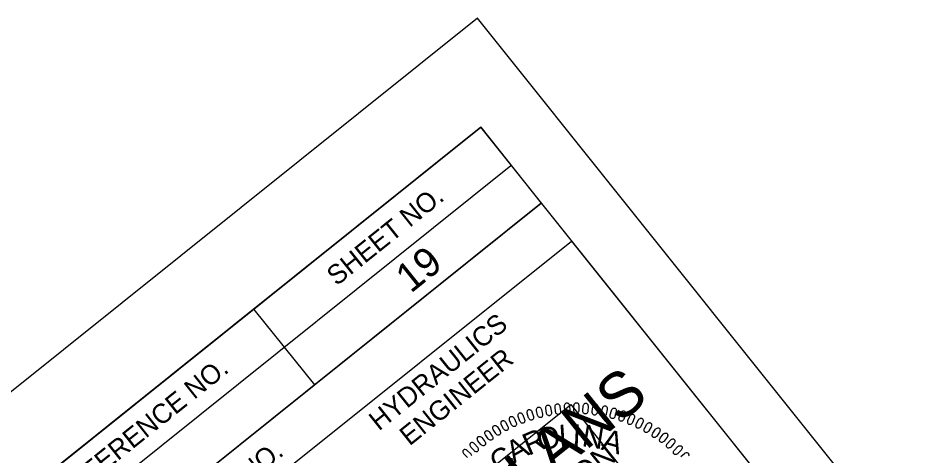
# Model space of a CAD drawing. Extents: x 472510 to 474509, y 505091 to 506998.
# Drawn here: x 473706 to 473939.9, y 506885.2 to 506998.1 of the extents above; entities that cross this region are included whole.
import ezdxf

# ---------------------------------------------------------------- set-up
doc = ezdxf.new("R2010")
doc.units = 0
for name, color, linetype in [('Sheet Data Field CELL', 7, 'Continuous'), ('Sheet PE Seal Cell', 7, 'Continuous'), ('Sheet Plan CELL', 7, 'Continuous'), ('Sheet Plot Border Outside CELL', 7, 'Continuous'), ('Sheet Sticker Incomplete CELL', 7, 'Continuous')]:
    doc.layers.add(name, color=color, linetype=linetype)

msp = doc.modelspace()

# ---------------------------------------------------------------- linework, layer by layer
at = {"layer": 'Sheet PE Seal Cell'}
for points in [[(473847.16, 506896.85), (473847.11, 506898.07), (473847.13, 506898.29), (473847.18, 506898.44), (473847.28, 506898.61), (473847.38, 506898.72), (473847.48, 506898.81), (473847.59, 506898.85), (473847.7, 506898.88), (473847.81, 506898.86), (473847.93, 506898.84), (473848.04, 506898.78), (473848.15, 506898.69), (473848.21, 506898.61), (473848.29, 506898.47), (473848.35, 506898.29), (473848.38, 506898.13), (473848.45, 506896.88), (473848.44, 506896.71), (473848.4, 506896.56), (473848.32, 506896.4), (473848.21, 506896.26), (473848.12, 506896.17), (473847.96, 506896.11), (473847.81, 506896.08), (473847.66, 506896.11), (473847.56, 506896.16), (473847.42, 506896.25), (473847.3, 506896.41), (473847.22, 506896.59), (473847.19, 506896.72)], [(473849.53, 506896.92), (473849.55, 506898.15), (473849.59, 506898.37), (473849.64, 506898.51), (473849.76, 506898.68), (473849.86, 506898.78), (473849.97, 506898.86), (473850.08, 506898.9), (473850.19, 506898.92), (473850.3, 506898.9), (473850.42, 506898.87), (473850.52, 506898.8), (473850.63, 506898.7), (473850.69, 506898.62), (473850.75, 506898.47), (473850.81, 506898.29), (473850.83, 506898.13), (473850.81, 506896.87), (473850.79, 506896.7), (473850.74, 506896.57), (473850.65, 506896.41), (473850.53, 506896.27), (473850.44, 506896.19), (473850.28, 506896.13), (473850.13, 506896.12), (473849.98, 506896.16), (473849.88, 506896.21), (473849.75, 506896.31), (473849.63, 506896.48), (473849.57, 506896.67), (473849.54, 506896.8)], [(473851.86, 506896.85), (473851.96, 506898.07), (473852.01, 506898.29), (473852.07, 506898.42), (473852.2, 506898.58), (473852.3, 506898.69), (473852.42, 506898.76), (473852.53, 506898.79), (473852.64, 506898.8), (473852.75, 506898.77), (473852.87, 506898.73), (473852.97, 506898.66), (473853.07, 506898.55), (473853.12, 506898.47), (473853.17, 506898.32), (473853.22, 506898.13), (473853.23, 506897.97), (473853.14, 506896.72), (473853.1, 506896.55), (473853.05, 506896.42), (473852.94, 506896.26), (473852.82, 506896.13), (473852.72, 506896.06), (473852.56, 506896.01), (473852.41, 506896.01), (473852.26, 506896.06), (473852.16, 506896.12), (473852.04, 506896.23), (473851.93, 506896.4), (473851.88, 506896.59), (473851.86, 506896.72)], [(473837.83, 506895.02), (473837.47, 506896.2), (473837.45, 506896.42), (473837.45, 506896.57), (473837.51, 506896.76), (473837.57, 506896.9), (473837.66, 506897), (473837.75, 506897.07), (473837.85, 506897.13), (473837.96, 506897.14), (473838.08, 506897.15), (473838.2, 506897.12), (473838.33, 506897.05), (473838.41, 506897), (473838.52, 506896.87), (473838.63, 506896.72), (473838.7, 506896.57), (473839.07, 506895.37), (473839.1, 506895.2), (473839.1, 506895.06), (473839.06, 506894.88), (473838.99, 506894.71), (473838.92, 506894.61), (473838.79, 506894.5), (473838.65, 506894.44), (473838.5, 506894.44), (473838.38, 506894.45), (473838.23, 506894.51), (473838.07, 506894.64), (473837.95, 506894.79), (473837.89, 506894.91)], [(473840.17, 506895.7), (473839.88, 506896.89), (473839.87, 506897.11), (473839.89, 506897.26), (473839.96, 506897.45), (473840.02, 506897.58), (473840.12, 506897.68), (473840.21, 506897.75), (473840.31, 506897.79), (473840.43, 506897.8), (473840.55, 506897.8), (473840.66, 506897.76), (473840.79, 506897.69), (473840.87, 506897.63), (473840.97, 506897.5), (473841.07, 506897.34), (473841.13, 506897.19), (473841.43, 506895.97), (473841.44, 506895.8), (473841.43, 506895.65), (473841.38, 506895.47), (473841.3, 506895.31), (473841.23, 506895.21), (473841.09, 506895.12), (473840.95, 506895.06), (473840.8, 506895.07), (473840.68, 506895.09), (473840.53, 506895.16), (473840.38, 506895.3), (473840.27, 506895.45), (473840.21, 506895.57)], [(473842.46, 506896.23), (473842.25, 506897.44), (473842.25, 506897.66), (473842.28, 506897.81), (473842.36, 506897.99), (473842.44, 506898.12), (473842.53, 506898.22), (473842.63, 506898.27), (473842.74, 506898.31), (473842.85, 506898.31), (473842.97, 506898.3), (473843.09, 506898.26), (473843.21, 506898.18), (473843.28, 506898.11), (473843.37, 506897.98), (473843.46, 506897.81), (473843.51, 506897.66), (473843.73, 506896.42), (473843.74, 506896.25), (473843.72, 506896.1), (473843.66, 506895.93), (473843.57, 506895.78), (473843.49, 506895.68), (473843.34, 506895.59), (473843.2, 506895.55), (473843.05, 506895.56), (473842.94, 506895.59), (473842.79, 506895.67), (473842.65, 506895.82), (473842.55, 506895.98), (473842.5, 506896.11)], [(473844.81, 506896.59), (473844.67, 506897.81), (473844.69, 506898.03), (473844.72, 506898.18), (473844.82, 506898.36), (473844.9, 506898.48), (473845, 506898.57), (473845.1, 506898.62), (473845.21, 506898.65), (473845.33, 506898.64), (473845.45, 506898.63), (473845.56, 506898.58), (473845.67, 506898.49), (473845.74, 506898.42), (473845.83, 506898.28), (473845.91, 506898.11), (473845.94, 506897.95), (473846.09, 506896.7), (473846.08, 506896.53), (473846.06, 506896.39), (473845.98, 506896.22), (473845.89, 506896.07), (473845.8, 506895.98), (473845.65, 506895.9), (473845.5, 506895.87), (473845.35, 506895.89), (473845.24, 506895.93), (473845.1, 506896.01), (473844.97, 506896.17), (473844.88, 506896.34), (473844.84, 506896.46)], [(473854.28, 506896.62), (473854.45, 506897.83), (473854.52, 506898.04), (473854.59, 506898.17), (473854.73, 506898.33), (473854.84, 506898.42), (473854.96, 506898.48), (473855.07, 506898.51), (473855.18, 506898.51), (473855.29, 506898.48), (473855.41, 506898.43), (473855.5, 506898.36), (473855.59, 506898.24), (473855.64, 506898.16), (473855.68, 506898), (473855.72, 506897.81), (473855.72, 506897.65), (473855.55, 506896.41), (473855.5, 506896.24), (473855.44, 506896.11), (473855.32, 506895.96), (473855.19, 506895.84), (473855.09, 506895.78), (473854.92, 506895.74), (473854.77, 506895.74), (473854.63, 506895.8), (473854.53, 506895.87), (473854.42, 506895.98), (473854.33, 506896.17), (473854.29, 506896.36), (473854.27, 506896.49)], [(473856.63, 506896.26), (473856.88, 506897.46), (473856.96, 506897.67), (473857.04, 506897.8), (473857.18, 506897.94), (473857.3, 506898.03), (473857.43, 506898.08), (473857.54, 506898.1), (473857.65, 506898.1), (473857.76, 506898.05), (473857.87, 506898), (473857.96, 506897.92), (473858.04, 506897.8), (473858.08, 506897.71), (473858.12, 506897.55), (473858.14, 506897.36), (473858.13, 506897.2), (473857.88, 506895.97), (473857.82, 506895.81), (473857.75, 506895.68), (473857.63, 506895.54), (473857.49, 506895.43), (473857.38, 506895.37), (473857.22, 506895.34), (473857.07, 506895.36), (473856.93, 506895.43), (473856.84, 506895.5), (473856.73, 506895.62), (473856.65, 506895.81), (473856.62, 506896), (473856.62, 506896.13)], [(473858.91, 506895.75), (473859.23, 506896.93), (473859.33, 506897.14), (473859.41, 506897.26), (473859.57, 506897.39), (473859.69, 506897.47), (473859.82, 506897.52), (473859.93, 506897.53), (473860.04, 506897.52), (473860.15, 506897.47), (473860.25, 506897.41), (473860.34, 506897.32), (473860.41, 506897.2), (473860.45, 506897.11), (473860.47, 506896.94), (473860.48, 506896.76), (473860.46, 506896.6), (473860.14, 506895.38), (473860.07, 506895.22), (473859.99, 506895.1), (473859.86, 506894.97), (473859.72, 506894.87), (473859.6, 506894.82), (473859.44, 506894.8), (473859.29, 506894.82), (473859.15, 506894.9), (473859.07, 506894.97), (473858.97, 506895.1), (473858.9, 506895.3), (473858.88, 506895.49), (473858.89, 506895.62)], [(473861.22, 506895.11), (473861.61, 506896.27), (473861.72, 506896.46), (473861.82, 506896.58), (473861.98, 506896.7), (473862.1, 506896.77), (473862.24, 506896.81), (473862.35, 506896.82), (473862.46, 506896.8), (473862.56, 506896.74), (473862.66, 506896.68), (473862.74, 506896.59), (473862.81, 506896.46), (473862.84, 506896.36), (473862.86, 506896.2), (473862.85, 506896.01), (473862.82, 506895.85), (473862.42, 506894.66), (473862.35, 506894.51), (473862.26, 506894.39), (473862.12, 506894.27), (473861.97, 506894.17), (473861.85, 506894.13), (473861.68, 506894.12), (473861.54, 506894.15), (473861.41, 506894.24), (473861.33, 506894.32), (473861.24, 506894.46), (473861.18, 506894.66), (473861.17, 506894.85), (473861.19, 506894.98)], [(473831.35, 506892.18), (473830.78, 506893.27), (473830.71, 506893.48), (473830.69, 506893.62), (473830.71, 506893.83), (473830.74, 506893.97), (473830.81, 506894.09), (473830.88, 506894.18), (473830.97, 506894.25), (473831.08, 506894.28), (473831.2, 506894.31), (473831.32, 506894.31), (473831.46, 506894.27), (473831.55, 506894.23), (473831.68, 506894.12), (473831.81, 506893.99), (473831.91, 506893.86), (473832.5, 506892.76), (473832.56, 506892.59), (473832.59, 506892.45), (473832.58, 506892.27), (473832.55, 506892.09), (473832.5, 506891.98), (473832.39, 506891.85), (473832.27, 506891.76), (473832.12, 506891.73), (473832, 506891.72), (473831.84, 506891.75), (473831.66, 506891.85), (473831.51, 506891.97), (473831.43, 506892.07)], [(473833.45, 506893.25), (473832.94, 506894.37), (473832.89, 506894.58), (473832.88, 506894.73), (473832.91, 506894.94), (473832.95, 506895.07), (473833.02, 506895.19), (473833.1, 506895.27), (473833.2, 506895.34), (473833.31, 506895.37), (473833.43, 506895.39), (473833.55, 506895.38), (473833.68, 506895.33), (473833.77, 506895.28), (473833.89, 506895.17), (473834.02, 506895.03), (473834.11, 506894.9), (473834.63, 506893.75), (473834.68, 506893.59), (473834.7, 506893.44), (473834.68, 506893.26), (473834.64, 506893.09), (473834.58, 506892.97), (473834.46, 506892.86), (473834.33, 506892.78), (473834.18, 506892.75), (473834.07, 506892.75), (473833.91, 506892.79), (473833.73, 506892.9), (473833.59, 506893.03), (473833.51, 506893.14)], [(473835.59, 506894.17), (473835.16, 506895.32), (473835.12, 506895.54), (473835.12, 506895.69), (473835.16, 506895.89), (473835.21, 506896.02), (473835.29, 506896.14), (473835.38, 506896.21), (473835.47, 506896.27), (473835.58, 506896.29), (473835.71, 506896.3), (473835.83, 506896.29), (473835.96, 506896.23), (473836.04, 506896.17), (473836.16, 506896.06), (473836.28, 506895.91), (473836.36, 506895.77), (473836.81, 506894.6), (473836.85, 506894.43), (473836.85, 506894.28), (473836.82, 506894.1), (473836.77, 506893.93), (473836.71, 506893.82), (473836.58, 506893.71), (473836.45, 506893.64), (473836.29, 506893.63), (473836.18, 506893.64), (473836.02, 506893.68), (473835.85, 506893.8), (473835.73, 506893.94), (473835.65, 506894.06)], [(473863.48, 506894.29), (473863.95, 506895.43), (473864.07, 506895.62), (473864.17, 506895.72), (473864.34, 506895.84), (473864.47, 506895.9), (473864.61, 506895.93), (473864.72, 506895.93), (473864.83, 506895.91), (473864.93, 506895.84), (473865.02, 506895.77), (473865.1, 506895.68), (473865.16, 506895.54), (473865.18, 506895.45), (473865.19, 506895.28), (473865.17, 506895.09), (473865.13, 506894.94), (473864.66, 506893.77), (473864.57, 506893.63), (473864.48, 506893.51), (473864.33, 506893.4), (473864.18, 506893.32), (473864.06, 506893.28), (473863.89, 506893.28), (473863.74, 506893.32), (473863.62, 506893.42), (473863.54, 506893.5), (473863.46, 506893.64), (473863.42, 506893.85), (473863.42, 506894.04), (473863.45, 506894.17)], [(473865.65, 506893.36), (473866.19, 506894.46), (473866.32, 506894.64), (473866.43, 506894.74), (473866.6, 506894.85), (473866.74, 506894.9), (473866.87, 506894.92), (473866.99, 506894.91), (473867.1, 506894.88), (473867.19, 506894.82), (473867.28, 506894.74), (473867.35, 506894.64), (473867.4, 506894.5), (473867.42, 506894.4), (473867.41, 506894.24), (473867.39, 506894.05), (473867.34, 506893.9), (473866.79, 506892.77), (473866.69, 506892.62), (473866.59, 506892.52), (473866.44, 506892.42), (473866.28, 506892.34), (473866.16, 506892.31), (473865.99, 506892.33), (473865.85, 506892.37), (473865.73, 506892.48), (473865.66, 506892.57), (473865.59, 506892.71), (473865.55, 506892.92), (473865.57, 506893.11), (473865.6, 506893.24)], [(473827.39, 506889.6), (473826.69, 506890.61), (473826.59, 506890.81), (473826.55, 506890.95), (473826.55, 506891.16), (473826.57, 506891.3), (473826.61, 506891.43), (473826.67, 506891.52), (473826.75, 506891.61), (473826.86, 506891.65), (473826.97, 506891.7), (473827.09, 506891.71), (473827.24, 506891.69), (473827.33, 506891.66), (473827.47, 506891.57), (473827.62, 506891.46), (473827.73, 506891.34), (473828.46, 506890.32), (473828.54, 506890.17), (473828.58, 506890.03), (473828.6, 506889.84), (473828.59, 506889.67), (473828.56, 506889.54), (473828.46, 506889.4), (473828.35, 506889.3), (473828.21, 506889.25), (473828.09, 506889.23), (473827.93, 506889.24), (473827.74, 506889.31), (473827.58, 506889.42), (473827.48, 506889.51)], [(473829.35, 506890.94), (473828.71, 506891.99), (473828.62, 506892.2), (473828.6, 506892.34), (473828.6, 506892.55), (473828.63, 506892.69), (473828.68, 506892.82), (473828.75, 506892.91), (473828.84, 506892.98), (473828.94, 506893.02), (473829.06, 506893.06), (473829.18, 506893.06), (473829.32, 506893.03), (473829.41, 506893), (473829.55, 506892.9), (473829.69, 506892.78), (473829.8, 506892.66), (473830.46, 506891.59), (473830.53, 506891.43), (473830.56, 506891.29), (473830.57, 506891.11), (473830.55, 506890.93), (473830.51, 506890.81), (473830.4, 506890.68), (473830.29, 506890.58), (473830.14, 506890.54), (473830.02, 506890.53), (473829.86, 506890.54), (473829.67, 506890.63), (473829.52, 506890.75), (473829.43, 506890.84)], [(473867.76, 506892.28), (473868.37, 506893.35), (473868.51, 506893.52), (473868.63, 506893.62), (473868.81, 506893.71), (473868.95, 506893.76), (473869.08, 506893.77), (473869.2, 506893.75), (473869.3, 506893.71), (473869.39, 506893.64), (473869.48, 506893.56), (473869.54, 506893.45), (473869.58, 506893.31), (473869.59, 506893.21), (473869.58, 506893.05), (473869.54, 506892.86), (473869.48, 506892.72), (473868.86, 506891.62), (473868.76, 506891.48), (473868.65, 506891.39), (473868.5, 506891.29), (473868.33, 506891.23), (473868.2, 506891.2), (473868.04, 506891.23), (473867.9, 506891.29), (473867.79, 506891.4), (473867.72, 506891.49), (473867.66, 506891.64), (473867.64, 506891.85), (473867.67, 506892.04), (473867.71, 506892.16)], [(473869.89, 506891.02), (473870.57, 506892.05), (473870.72, 506892.21), (473870.84, 506892.3), (473871.02, 506892.38), (473871.17, 506892.42), (473871.3, 506892.42), (473871.41, 506892.4), (473871.52, 506892.35), (473871.6, 506892.28), (473871.68, 506892.18), (473871.74, 506892.08), (473871.77, 506891.94), (473871.78, 506891.84), (473871.75, 506891.67), (473871.7, 506891.49), (473871.63, 506891.35), (473870.95, 506890.29), (473870.84, 506890.16), (473870.72, 506890.07), (473870.56, 506889.99), (473870.39, 506889.93), (473870.26, 506889.92), (473870.1, 506889.95), (473869.96, 506890.02), (473869.86, 506890.14), (473869.8, 506890.24), (473869.75, 506890.39), (473869.74, 506890.6), (473869.79, 506890.78), (473869.83, 506890.91)], [(473825.53, 506888.15), (473824.77, 506889.11), (473824.66, 506889.3), (473824.61, 506889.45), (473824.59, 506889.65), (473824.6, 506889.79), (473824.64, 506889.93), (473824.7, 506890.02), (473824.77, 506890.11), (473824.87, 506890.16), (473824.98, 506890.21), (473825.1, 506890.23), (473825.25, 506890.22), (473825.34, 506890.19), (473825.49, 506890.12), (473825.65, 506890.02), (473825.77, 506889.91), (473826.56, 506888.93), (473826.64, 506888.78), (473826.7, 506888.65), (473826.73, 506888.47), (473826.73, 506888.29), (473826.7, 506888.16), (473826.61, 506888.02), (473826.51, 506887.91), (473826.37, 506887.85), (473826.26, 506887.82), (473826.09, 506887.82), (473825.89, 506887.88), (473825.73, 506887.98), (473825.63, 506888.06)], [(473871.83, 506889.79), (473872.57, 506890.77), (473872.73, 506890.93), (473872.86, 506891.01), (473873.05, 506891.07), (473873.19, 506891.1), (473873.33, 506891.1), (473873.44, 506891.07), (473873.54, 506891.02), (473873.62, 506890.93), (473873.69, 506890.84), (473873.74, 506890.73), (473873.76, 506890.59), (473873.76, 506890.49), (473873.73, 506890.33), (473873.67, 506890.15), (473873.59, 506890), (473872.84, 506889), (473872.72, 506888.87), (473872.6, 506888.79), (473872.43, 506888.72), (473872.26, 506888.67), (473872.13, 506888.67), (473871.97, 506888.71), (473871.84, 506888.79), (473871.75, 506888.91), (473871.69, 506889.01), (473871.65, 506889.17), (473871.66, 506889.37), (473871.71, 506889.56), (473871.77, 506889.68)], [(473873.64, 506888.35), (473874.43, 506889.28), (473874.61, 506889.43), (473874.74, 506889.5), (473874.93, 506889.55), (473875.08, 506889.57), (473875.21, 506889.56), (473875.32, 506889.52), (473875.42, 506889.47), (473875.49, 506889.38), (473875.56, 506889.28), (473875.6, 506889.16), (473875.62, 506889.02), (473875.61, 506888.92), (473875.56, 506888.76), (473875.49, 506888.59), (473875.41, 506888.45), (473874.59, 506887.49), (473874.47, 506887.38), (473874.34, 506887.3), (473874.17, 506887.24), (473873.99, 506887.21), (473873.87, 506887.21), (473873.71, 506887.26), (473873.58, 506887.35), (473873.5, 506887.47), (473873.45, 506887.58), (473873.42, 506887.74), (473873.44, 506887.94), (473873.5, 506888.13), (473873.56, 506888.24)], [(473824.67, 506887.45), (473823.84, 506888.35), (473823.67, 506888.49), (473823.54, 506888.56), (473823.34, 506888.61), (473823.19, 506888.63), (473823.06, 506888.61), (473822.95, 506888.57), (473822.86, 506888.51), (473822.79, 506888.42), (473822.72, 506888.32), (473822.68, 506888.2), (473822.67, 506888.06), (473822.68, 506887.96), (473822.73, 506887.8), (473822.81, 506887.63), (473822.9, 506887.49), (473823.74, 506886.56), (473823.87, 506886.45), (473823.99, 506886.38), (473824.17, 506886.32), (473824.35, 506886.29), (473824.47, 506886.3), (473824.63, 506886.36), (473824.75, 506886.44), (473824.84, 506886.57), (473824.88, 506886.68), (473824.91, 506886.84), (473824.88, 506887.05), (473824.81, 506887.22), (473824.74, 506887.34)], [(473875.47, 506886.7), (473876.33, 506887.58), (473876.51, 506887.71), (473876.64, 506887.77), (473876.84, 506887.81), (473876.99, 506887.83), (473877.12, 506887.81), (473877.22, 506887.76), (473877.32, 506887.7), (473877.39, 506887.6), (473877.45, 506887.5), (473877.48, 506887.38), (473877.49, 506887.24), (473877.48, 506887.14), (473877.42, 506886.99), (473877.34, 506886.82), (473877.24, 506886.69), (473876.37, 506885.78), (473876.24, 506885.67), (473876.11, 506885.6), (473875.93, 506885.55), (473875.76, 506885.53), (473875.63, 506885.54), (473875.48, 506885.61), (473875.36, 506885.7), (473875.28, 506885.83), (473875.24, 506885.94), (473875.21, 506886.1), (473875.25, 506886.3), (473875.32, 506886.48), (473875.39, 506886.59)]]:
    msp.add_lwpolyline(points, close=True, dxfattribs=at)
for points in [[(473823.17, 506885.17), (473823.13, 506885.38), (473823.05, 506885.55), (473822.97, 506885.66), (473822.89, 506885.76), (473822.01, 506886.62), (473821.83, 506886.75), (473821.69, 506886.8), (473821.49, 506886.84), (473821.34, 506886.85), (473821.21, 506886.82), (473821.11, 506886.78), (473821.02, 506886.71), (473820.95, 506886.62), (473820.89, 506886.51), (473820.86, 506886.39), (473820.86, 506886.25), (473820.87, 506886.15), (473820.93, 506886), (473821.02, 506885.83), (473821.12, 506885.7), (473822.02, 506884.82)], [(473877.14, 506885), (473878.05, 506885.83), (473878.24, 506885.95), (473878.37, 506886), (473878.57, 506886.03), (473878.72, 506886.03), (473878.86, 506886), (473878.96, 506885.95), (473879.05, 506885.88), (473879.11, 506885.79), (473879.16, 506885.68), (473879.19, 506885.56), (473879.19, 506885.42), (473879.17, 506885.32), (473879.1, 506885.17)]]:
    msp.add_lwpolyline(points, dxfattribs=at)
at = {"layer": 'Sheet Plan CELL'}
for p, q in [((473677.09, 506835.14), (473833.29, 506960.13)), ((473684.94, 506825.36), (473841.1, 506950.37)), ((473684.94, 506825.36), (473841.1, 506950.37)), ((473766.91, 506923), (473782.57, 506903.52))]:
    msp.add_line(p, q, dxfattribs=at)
for points in [[(473825.47, 506969.95), (472654.33, 506032.66), (473310.42, 505212.87), (474481.55, 506150.16)], [(473669.26, 506844.95), (473825.47, 506969.95), (473841.1, 506950.37), (473684.94, 506825.36)], [(473770.85, 506878.13), (473848.91, 506940.61), (473919.22, 506852.78), (473841.16, 506790.28)]]:
    msp.add_lwpolyline(points, close=True, dxfattribs=at)
at = {"layer": 'Sheet Plot Border Outside CELL'}
msp.add_lwpolyline([(473194.51, 505091.27), (474508.89, 506143.2), (473824.68, 506998.12), (472510.29, 505946.18)], close=True, dxfattribs=at)
at = {"layer": 'Sheet Sticker Incomplete CELL'}
msp.add_lwpolyline([(473748.62, 506788.28), (473733.93, 506806.63), (473848.7, 506898.48), (473863.38, 506880.14)], close=True, dxfattribs=at)

# ---------------------------------------------------------------- texts
at = {"layer": 'Sheet Data Field CELL'}
msp.add_text('19', height=7.5, rotation=38.6712, dxfattribs=at).set_placement((473807.4, 506926.99))
at = {"layer": 'Sheet PE Seal Cell'}
for s, rotation, p in [('R', 23.2802, (473837.84, 506885.18)), ('O', 10.3015, (473840.56, 506886.52)), ('L', 3.8121, (473845.84, 506887.5)), ('I', 357.3228, (473849.1, 506887.74)), ('N', 350.8334, (473851.39, 506887.76)), ('A', 344.344, (473856.35, 506886.88)), ('A', 29.7695, (473834.06, 506883.17)), ('C', 36.2589, (473830.36, 506880.48))]:
    msp.add_text(s, height=5.67, rotation=rotation, dxfattribs=at).set_placement(p)
at = {"layer": 'Sheet Plan CELL'}
for s, height, p in [('SHEET NO.', 5, (473788.27, 506928.88)), ('HYDRAULICS', 5, (473799.18, 506891.48)), ('ENGINEER', 5, (473807.09, 506887.62)), ('PROJECT REFERENCE NO.', 5.0001, (473692.04, 506852.01)), ('R/W SHEET NO.', 5.0001, (473735.18, 506853.8))]:
    msp.add_text(s, height=height, rotation=38.6712, dxfattribs=at).set_placement(p)
at = {"layer": 'Sheet Sticker Incomplete CELL'}
for s, height, p in [('INCOMPLETE PLANS', 11.52, (473748.29, 506803.01)), ('DO NOT USE FOR R/W ACQUISITION', 5.76, (473755.17, 506799.62))]:
    msp.add_text(s, height=height, rotation=38.6712, dxfattribs=at).set_placement(p)

doc.saveas('drawing.dxf')
